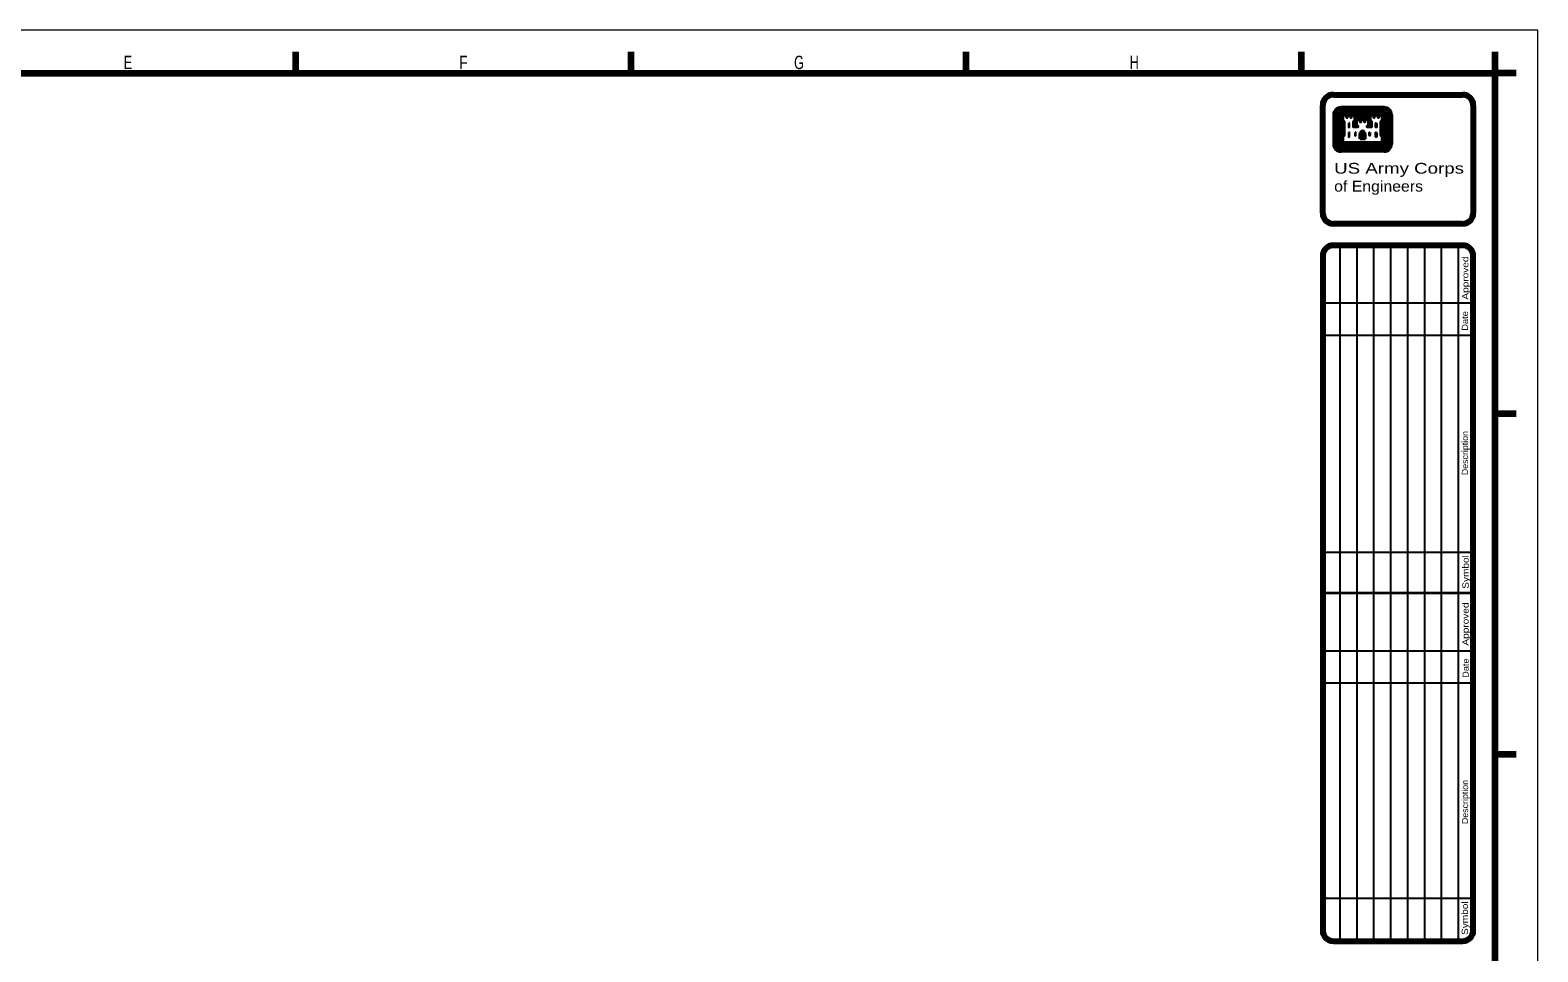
# Model space of a CAD drawing. Extents: x -202666 to -201825, y -108963 to -108369.
# Drawn here: x -202245.6 to -201825.1, y -108626.4 to -108369.4 of the extents above; entities that cross this region are included whole.
import ezdxf
from ezdxf.enums import TextEntityAlignment as Align

# ---------------------------------------------------------------- set-up
doc = ezdxf.new("R2010")
doc.units = 0
doc.header["$LTSCALE"] = 0.8
doc.layers.add('1', color=7, linetype='Continuous', lineweight=35)

msp = doc.modelspace()

# ---------------------------------------------------------------- linework, layer by layer
at = {"layer": '1', "lineweight": 90}
for p, q in [((-202171.613, -108375.444), (-202171.613, -108381.444)), ((-202078.113, -108375.444), (-202078.113, -108381.444)), ((-201984.613, -108375.444), (-201984.613, -108381.444)), ((-201891.113, -108375.444), (-201891.113, -108381.444)), ((-201831.113, -108381.444), (-201837.113, -108381.444)), ((-201831.113, -108476.444), (-201837.113, -108476.444)), ((-201831.113, -108571.444), (-201837.113, -108571.444))]:
    msp.add_line(p, q, dxfattribs=at)
at = {"layer": '1', "lineweight": 80}
for p, q in [((-201882.113, -108387.444), (-201846.113, -108387.444)), ((-201885.113, -108420.444), (-201885.113, -108390.444)), ((-201843.113, -108390.444), (-201843.113, -108420.444)), ((-201846.113, -108423.444), (-201882.113, -108423.444)), ((-201846.114, -108429.469), (-201882.113, -108429.469)), ((-201885.113, -108432.469), (-201885.113, -108620.469)), ((-201843.114, -108620.469), (-201843.114, -108432.469)), ((-201882.113, -108623.469), (-201846.114, -108623.469))]:
    msp.add_line(p, q, dxfattribs=at)
at = {"layer": '1'}
for p, q in [((-201867.993, -108390.944), (-201880.003, -108390.944)), ((-201867.993, -108391.064), (-201880.003, -108391.064)), ((-201867.993, -108391.234), (-201880.003, -108391.234)), ((-201867.993, -108391.404), (-201880.003, -108391.404)), ((-201867.993, -108391.574), (-201880.003, -108391.574)), ((-201867.993, -108392.254), (-201880.003, -108392.254)), ((-201882.143, -108393.074), (-201882.143, -108401.194)), ((-201882.023, -108393.074), (-201882.023, -108401.194)), ((-201881.833, -108393.074), (-201881.833, -108401.194)), ((-201881.663, -108393.074), (-201881.663, -108401.194)), ((-201881.503, -108393.074), (-201881.503, -108401.194)), ((-201880.803, -108393.074), (-201880.803, -108401.194)), ((-201880.633, -108393.074), (-201880.633, -108401.194)), ((-201880.463, -108393.074), (-201880.463, -108401.194)), ((-201880.293, -108393.074), (-201880.293, -108401.194)), ((-201880.113, -108393.074), (-201880.113, -108401.194)), ((-201867.993, -108392.444), (-201880.003, -108392.444)), ((-201867.993, -108392.614), (-201880.003, -108392.614)), ((-201867.993, -108392.784), (-201880.003, -108392.784)), ((-201867.993, -108392.954), (-201880.003, -108392.954)), ((-201879.953, -108393.074), (-201879.953, -108401.134)), ((-201879.783, -108393.074), (-201879.783, -108400.954)), ((-201879.643, -108394.804), (-201879.643, -108398.954)), ((-201879.463, -108394.974), (-201879.463, -108398.754)), ((-201875.853, -108393.124), (-201872.153, -108393.124)), ((-201875.853, -108393.284), (-201872.153, -108393.284)), ((-201875.853, -108393.444), (-201872.153, -108393.444)), ((-201875.853, -108393.624), (-201872.153, -108393.624)), ((-201875.853, -108393.794), (-201872.153, -108393.794)), ((-201875.853, -108393.964), (-201872.153, -108393.964)), ((-201875.853, -108394.144), (-201872.153, -108394.144)), ((-201868.523, -108394.974), (-201868.523, -108398.754)), ((-201868.373, -108394.814), (-201868.373, -108398.924)), ((-201868.213, -108393.074), (-201868.213, -108400.954)), ((-201868.053, -108393.074), (-201868.053, -108401.134)), ((-201867.883, -108393.074), (-201867.883, -108401.194)), ((-201867.703, -108393.074), (-201867.703, -108401.194)), ((-201867.533, -108393.074), (-201867.533, -108401.194)), ((-201867.373, -108393.074), (-201867.373, -108401.194)), ((-201867.193, -108393.074), (-201867.193, -108401.194)), ((-201866.503, -108393.074), (-201866.503, -108401.194)), ((-201866.333, -108393.074), (-201866.333, -108401.194)), ((-201866.163, -108393.074), (-201866.163, -108401.194)), ((-201865.993, -108393.074), (-201865.993, -108401.194)), ((-201865.863, -108393.074), (-201865.863, -108401.194)), ((-201874.803, -108399.784), (-201874.803, -108398.464)), ((-201874.803, -108399.784), (-201873.193, -108399.784)), ((-201874.633, -108399.784), (-201874.633, -108398.464)), ((-201874.453, -108399.784), (-201874.453, -108398.464)), ((-201874.293, -108399.784), (-201874.293, -108398.464)), ((-201874.103, -108399.784), (-201874.103, -108398.464)), ((-201873.883, -108399.784), (-201873.883, -108398.464)), ((-201873.723, -108399.784), (-201873.723, -108398.464)), ((-201873.543, -108399.784), (-201873.543, -108398.464)), ((-201873.373, -108399.784), (-201873.373, -108398.464)), ((-201873.193, -108399.784), (-201873.193, -108398.464)), ((-201867.993, -108401.314), (-201880.003, -108401.314)), ((-201867.993, -108401.474), (-201880.003, -108401.474)), ((-201867.993, -108401.654), (-201880.003, -108401.654)), ((-201867.993, -108401.824), (-201880.003, -108401.824)), ((-201867.993, -108401.994), (-201880.003, -108401.994)), ((-201867.993, -108402.694), (-201880.003, -108402.694)), ((-201867.993, -108402.864), (-201880.003, -108402.864)), ((-201867.993, -108403.014), (-201880.003, -108403.014)), ((-201867.993, -108403.194), (-201880.003, -108403.194)), ((-201867.993, -108403.324), (-201880.003, -108403.324)), ((-201868.053, -108401.134), (-201879.953, -108401.134)), ((-201868.213, -108400.954), (-201879.783, -108400.954)), ((-201843.114, -108526.469), (-201885.144, -108526.469))]:
    msp.add_line(p, q, dxfattribs=at)
at = {"layer": '1', "lineweight": 25}
for p, q in [((-201880.354, -108429.469), (-201880.354, -108623.469)), ((-201875.644, -108429.469), (-201875.644, -108623.469)), ((-201870.924, -108429.469), (-201870.924, -108623.469)), ((-201866.204, -108429.469), (-201866.204, -108623.469)), ((-201861.484, -108429.469), (-201861.484, -108623.469)), ((-201856.764, -108429.469), (-201856.764, -108623.469)), ((-201852.054, -108429.469), (-201852.054, -108623.469)), ((-201847.334, -108429.469), (-201847.334, -108623.469)), ((-201885.054, -108445.469), (-201843.114, -108445.469)), ((-201885.054, -108454.469), (-201843.114, -108454.469)), ((-201885.144, -108514.969), (-201843.114, -108514.969)), ((-201885.164, -108542.469), (-201843.114, -108542.469)), ((-201885.164, -108551.469), (-201843.114, -108551.469)), ((-201885.114, -108611.469), (-201843.114, -108611.469))]:
    msp.add_line(p, q, dxfattribs=at)
at = {"layer": '1', "lineweight": 13}
msp.add_lwpolyline([(-202666.113, -108963.444), (-201825.113, -108963.444), (-201825.113, -108369.444), (-202666.113, -108369.444)], close=True, dxfattribs=at)
at = {"layer": '1', "lineweight": 90}
for points in [[(-201837.113, -108375.444), (-201837.113, -108381.444), (-201837.113, -108951.444), (-201837.113, -108957.444)], [(-202639.113, -108381.444), (-201891.113, -108381.444), (-201837.113, -108381.444)]]:
    msp.add_lwpolyline(points, dxfattribs=at)
at = {"layer": '1'}
for points in [[(-201879.643, -108393.074), (-201879.643, -108394.624), (-201879.293, -108394.974), (-201879.293, -108398.754), (-201879.643, -108399.114), (-201879.643, -108400.834), (-201868.353, -108400.834), (-201868.353, -108399.114), (-201868.713, -108398.754), (-201868.713, -108394.974), (-201868.353, -108394.624), (-201868.353, -108393.074), (-201869.833, -108393.074), (-201871.003, -108393.074), (-201872.053, -108393.074), (-201872.053, -108394.624), (-201871.683, -108394.974), (-201871.683, -108396.344), (-201872.503, -108396.344), (-201872.503, -108396.214), (-201872.153, -108395.864), (-201872.153, -108394.324), (-201873.653, -108394.324), (-201874.783, -108394.324), (-201875.853, -108394.324), (-201875.853, -108395.864), (-201875.493, -108396.214), (-201875.493, -108396.344), (-201876.303, -108396.344), (-201876.303, -108394.974), (-201875.943, -108394.624), (-201875.943, -108393.074), (-201877.463, -108393.074), (-201878.603, -108393.074)], [(-201879.473, -108393.244), (-201879.473, -108394.554), (-201879.123, -108394.914), (-201879.123, -108398.824), (-201879.473, -108399.174), (-201879.473, -108400.654), (-201868.523, -108400.654), (-201868.523, -108399.174), (-201868.873, -108398.824), (-201868.873, -108394.914), (-201868.523, -108394.554), (-201868.523, -108393.244), (-201869.573, -108393.244), (-201869.573, -108393.854), (-201869.673, -108393.854), (-201869.673, -108393.244), (-201870.723, -108393.244), (-201870.723, -108393.854), (-201870.823, -108393.854), (-201870.823, -108393.244), (-201871.863, -108393.244), (-201871.863, -108394.554), (-201871.523, -108394.914), (-201871.523, -108396.524), (-201872.673, -108396.524), (-201872.673, -108396.144), (-201872.323, -108395.804), (-201872.323, -108394.474), (-201873.373, -108394.474), (-201873.373, -108395.104), (-201873.483, -108395.104), (-201873.483, -108394.474), (-201874.523, -108394.474), (-201874.523, -108395.104), (-201874.633, -108395.104), (-201874.633, -108394.474), (-201875.673, -108394.474), (-201875.673, -108395.804), (-201875.313, -108396.144), (-201875.313, -108396.524), (-201876.493, -108396.524), (-201876.493, -108394.914), (-201876.123, -108394.554), (-201876.123, -108393.244), (-201877.173, -108393.244), (-201877.173, -108393.854), (-201877.273, -108393.854), (-201877.273, -108393.244), (-201878.333, -108393.244), (-201878.333, -108393.854), (-201878.423, -108393.854), (-201878.423, -108393.244)], [(-201877.853, -108395.354), (-201877.853, -108396.524), (-201877.753, -108396.524), (-201877.753, -108395.354)], [(-201870.143, -108395.354), (-201870.143, -108396.524), (-201870.253, -108396.524), (-201870.253, -108395.354)], [(-201877.853, -108398.014), (-201877.853, -108399.164), (-201877.753, -108399.164), (-201877.753, -108398.014)], [(-201876.043, -108398.014), (-201876.043, -108398.804), (-201875.933, -108398.804), (-201875.933, -108398.014)], [(-201871.963, -108398.014), (-201871.963, -108398.804), (-201872.063, -108398.804), (-201872.063, -108398.014)], [(-201870.143, -108398.014), (-201870.143, -108399.164), (-201870.253, -108399.164), (-201870.253, -108398.014)]]:
    msp.add_lwpolyline(points, close=True, dxfattribs=at)
for points in [[(-201876.033, -108394.954), (-201876.143, -108395.054), (-201876.143, -108396.184), (-201875.773, -108396.184), (-201876.023, -108395.924), (-201876.023, -108394.934)], [(-201871.963, -108394.954), (-201871.863, -108395.054), (-201871.863, -108396.184), (-201872.223, -108396.184), (-201871.983, -108395.924), (-201871.983, -108394.934)]]:
    msp.add_lwpolyline(points, dxfattribs=at)
at = {"layer": '1', "lineweight": 80}
for centre, start, end in [((-201882.113, -108390.444), 90, 180), ((-201846.113, -108390.444), 0, 90), ((-201882.113, -108420.444), 180, 270), ((-201846.113, -108420.444), 270, 0), ((-201882.113, -108432.469), 90, 180), ((-201846.114, -108432.469), 0, 90), ((-201882.113, -108620.469), 180, 270), ((-201846.114, -108620.469), 270, 0)]:
    msp.add_arc(centre, 3, start, end, dxfattribs=at)
at = {"layer": '1'}
for centre, radius, start, end in [((-201880.0127, -108393.0664), 2.1221, 90, 180), ((-201880.0127, -108393.0664), 1.9993, 90, 180), ((-201880.0127, -108393.0664), 1.8274, 90, 180), ((-201880.0127, -108393.0664), 1.6554, 90, 180), ((-201880.0127, -108393.0664), 1.4835, 90, 180), ((-201880.0127, -108393.0664), 0.7958, 90, 180), ((-201867.9877, -108393.0664), 2.1221, 0, 90), ((-201867.9877, -108393.0664), 1.9993, 0, 90), ((-201867.9877, -108393.0664), 1.8274, 0, 90), ((-201867.9877, -108393.0664), 1.6554, 0, 90), ((-201867.9877, -108393.0664), 1.4835, 0, 90), ((-201867.9877, -108393.0664), 0.7958, 0, 90), ((-201880.0127, -108393.0664), 0.6239, 90, 180), ((-201880.0127, -108393.0664), 0.4519, 90, 180), ((-201880.0127, -108393.0664), 0.28, 90, 180), ((-201880.0127, -108393.0664), 0.1081, 90, 180), ((-201867.9877, -108393.0664), 0.6239, 0, 90), ((-201867.9877, -108393.0664), 0.4519, 0, 90), ((-201867.9877, -108393.0664), 0.28, 0, 90), ((-201867.9877, -108393.0664), 0.1081, 0, 90), ((-201873.7039, -108398.5474), 1.0999, 105.66805, 176.05748), ((-201873.7039, -108398.5474), 0.928, 103.46979, 176.05748), ((-201873.7039, -108398.5474), 0.7561, 103.46979, 176.05748), ((-201873.7039, -108398.5474), 0.5842, 103.46979, 176.05748), ((-201874.2965, -108398.5474), 0.4123, 3.94252, 76.53021), ((-201874.2965, -108398.5474), 0.5842, 3.94252, 76.53021), ((-201874.2965, -108398.5474), 0.7561, 3.94253, 76.53021), ((-201873.7039, -108398.5474), 0.4123, 103.46979, 176.05747), ((-201874.2965, -108398.5474), 0.928, 3.94252, 76.53021), ((-201874.2965, -108398.5474), 1.0999, 3.94252, 74.39486), ((-201880.0127, -108401.201), 2.1221, 180, 270), ((-201880.0127, -108401.201), 1.9993, 180, 270), ((-201880.0127, -108401.201), 1.8274, 180, 270), ((-201880.0127, -108401.201), 1.6554, 180, 270), ((-201880.0127, -108401.201), 1.4835, 180, 270), ((-201880.0127, -108401.201), 0.7958, 180, 270), ((-201880.0127, -108401.201), 0.6239, 180, 270), ((-201880.0127, -108401.201), 0.4519, 180, 270), ((-201880.0127, -108401.201), 0.28, 180, 270), ((-201880.0127, -108401.201), 0.1081, 180, 270), ((-201867.9877, -108401.201), 2.1221, 270, 0), ((-201867.9877, -108401.201), 0.7958, 270, 0), ((-201867.9877, -108401.201), 0.6239, 270, 0), ((-201867.9877, -108401.201), 0.4519, 270, 0), ((-201867.9877, -108401.201), 0.28, 270, 0), ((-201867.9877, -108401.201), 0.1081, 270, 0), ((-201867.9877, -108401.201), 1.4835, 270, 360), ((-201867.9877, -108401.201), 1.6554, 270, 360), ((-201867.9877, -108401.201), 1.8274, 270, 360), ((-201867.9877, -108401.201), 1.9993, 270, 360)]:
    msp.add_arc(centre, radius, start, end, dxfattribs=at)

# ---------------------------------------------------------------- texts
for s, width, p in [('E', 0.7, (-202218.349, -108380.319)), ('F', 0.75, (-202124.775, -108380.319)), ('G', 0.7, (-202031.186, -108380.319)), ('H', 0.7, (-201937.6715, -108380.319))]:
    msp.add_text(s, height=3.75, dxfattribs=dict(at, width=width)).set_placement(p, align=Align.CENTER)
for s, width, p in [('US Army Corps', 1.3, (-201881.924, -108409.457)), ('of Engineers', 1.1, (-201881.924, -108414.457))]:
    msp.add_text(s, height=3, dxfattribs=dict(at, width=width)).set_placement(p)
for s, width, p in [('Approved', 1.2, (-201844.49, -108444.576)), ('Date', 1.1, (-201844.57, -108453.239)), ('Description', 1.05, (-201844.571, -108493.524)), ('Symbol', 1.2, (-201844.4, -108525.202)), ('Approved', 1.2, (-201844.424, -108541.049)), ('Date', 1.1, (-201844.377, -108550.061)), ('Description', 1.05, (-201844.559, -108590.814)), ('Symbol', 1.2, (-201844.61, -108621.739))]:
    msp.add_text(s, height=1.75, rotation=90, dxfattribs=dict(at, width=width)).set_placement(p)

doc.saveas('drawing.dxf')
